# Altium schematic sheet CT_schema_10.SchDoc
size 274 x 160 mm
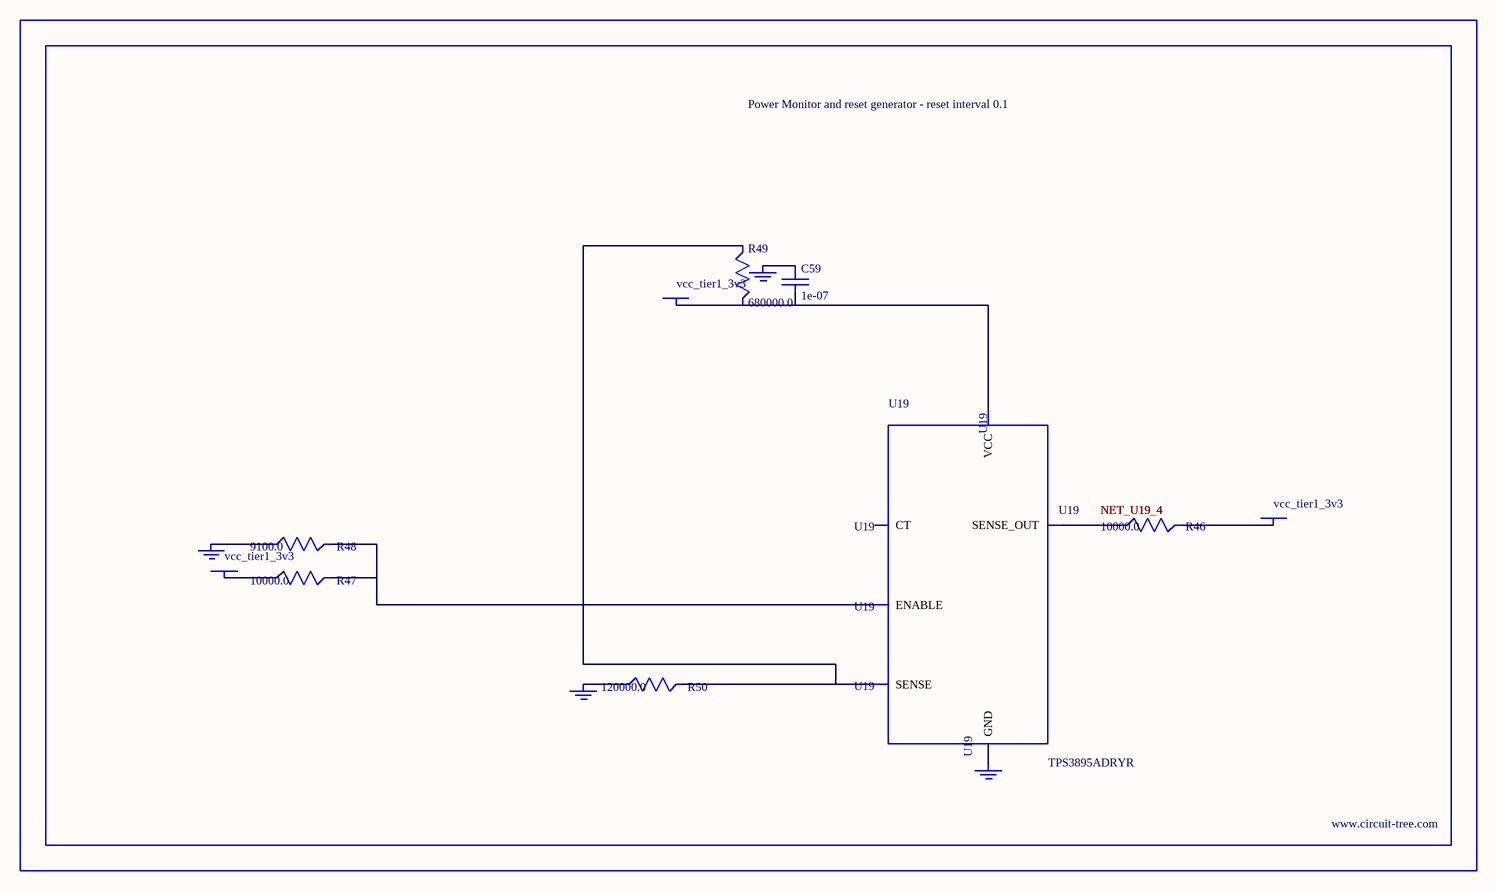
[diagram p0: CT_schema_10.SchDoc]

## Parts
BORDER9  (no value)
C59  1e-07  [C0402]
GND_INSTANCE_9_0  (no value)
GND_INSTANCE_9_1  (no value)
GND_INSTANCE_9_2  (no value)
GND_INSTANCE_9_3  (no value)
POWER_INSTANCE_9_0  vcc_tier1_3v3
POWER_INSTANCE_9_1  vcc_tier1_3v3
POWER_INSTANCE_9_2  vcc_tier1_3v3
R46  10000.0  [R0603]
R47  10000.0  [R0603]
R48  9100.0  [R0603]
R49  680000.0  [R0603]
R50  120000.0  [R0603]
U19  TPS3895ADRYR  [SON-6]

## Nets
NetC59_1: C59.1 GND_INSTANCE_9_2.0(GND)
NetC59_2: C59.2 POWER_INSTANCE_9_2.0(PWR) R49.2 U19.6(VCC)
NetGND_INSTANCE_9_0_0: GND_INSTANCE_9_0.0(GND) R48.1
NetGND_INSTANCE_9_1_0: GND_INSTANCE_9_1.0(GND) R50.1
NetGND_INSTANCE_9_3_0: GND_INSTANCE_9_3.0(GND) U19.2(GND)
NetPOWER_INSTANCE_9_0_0: POWER_INSTANCE_9_0.0(PWR) R47.1
NetPOWER_INSTANCE_9_1_0: POWER_INSTANCE_9_1.0(PWR) R46.2
NetR46_1: R46.1 U19.4(SENSE_OUT)
NetR47_2: R47.2 R48.2 U19.1(ENABLE)
NetR49_1: R49.1 R50.2 U19.3(SENSE)

Not connected (* = marked no-connect by the designer): U19 5(CT)

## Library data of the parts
BORDER9 = BORDER_PAGE9
C59 = C0402C104K3RACTU
GND_INSTANCE_9_0-GND_INSTANCE_9_3 = GND
POWER_INSTANCE_9_0-POWER_INSTANCE_9_2 = PWR
R46 R47 = RC0603JR-0710KL
R48 = RC0603JR-079K1L
R49 = RC0603JR-07680KL
R50 = RC0603JR-07120KL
